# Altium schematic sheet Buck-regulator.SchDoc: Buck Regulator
size A4; Organization: Team- Ashwathama; Address1: Colorado Boulder; Address2: Author- Satya Mehta; Address3: Self Checkout Shopping Cart; DocumentNumber: 1; Revision: 1.0; SheetNumber: 3; SheetTotal: 7
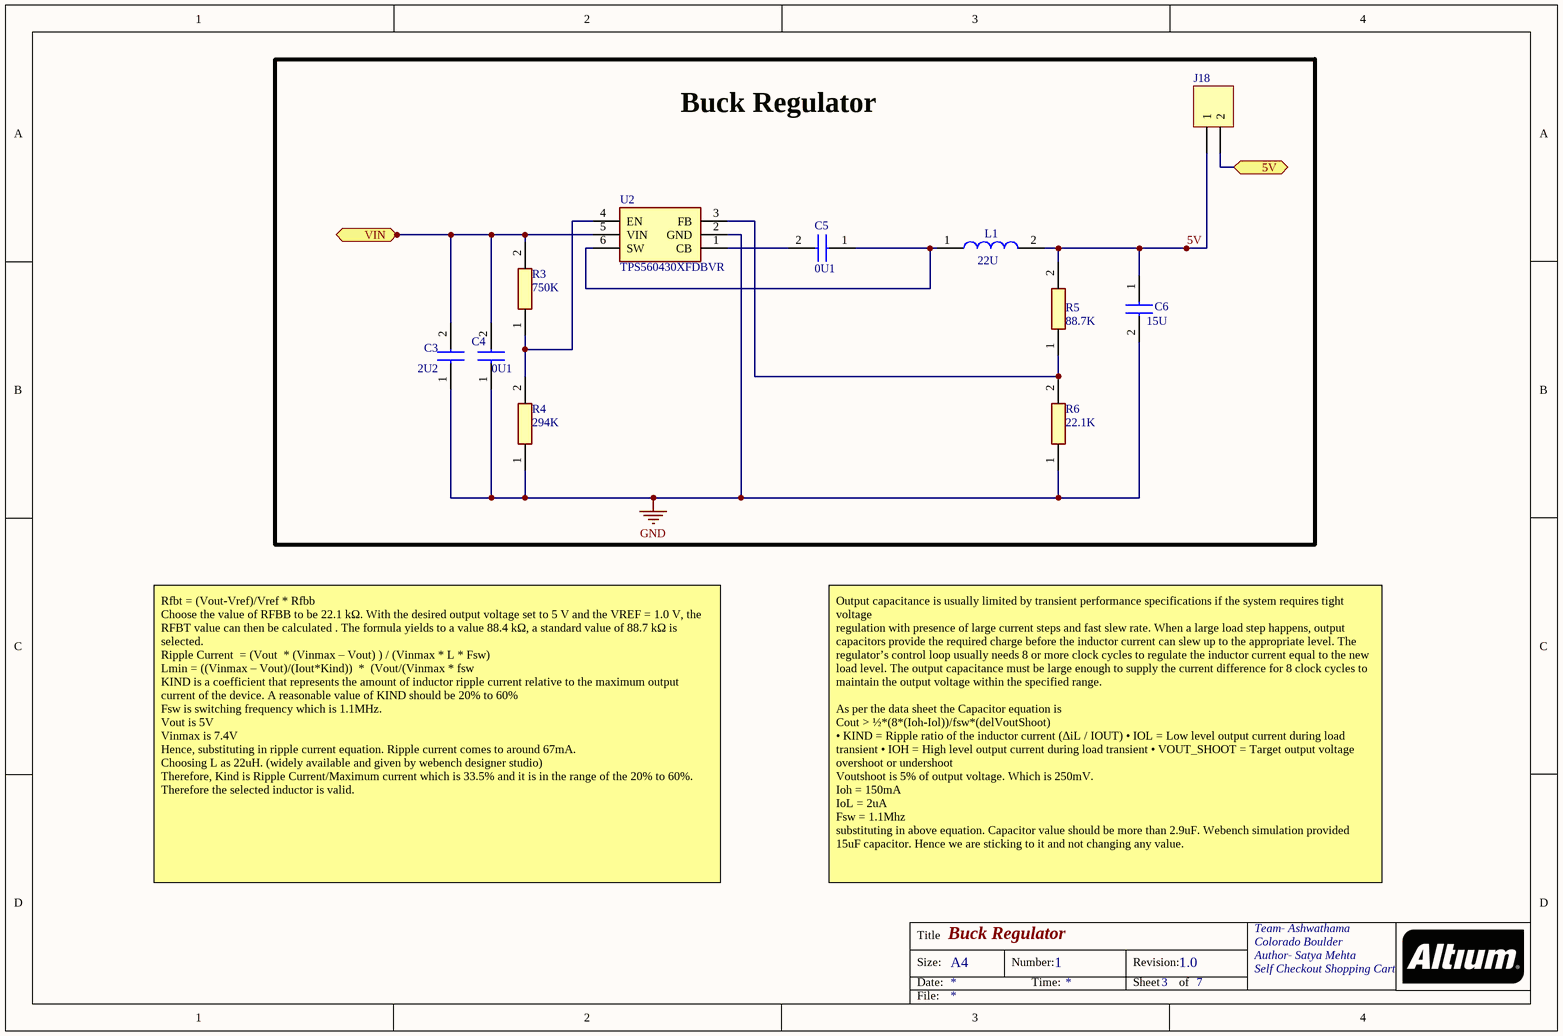
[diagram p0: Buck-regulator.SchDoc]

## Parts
C3  value 2U2  [CAPC2012X145N]  (hidden comment: GRM21BR71C225KA12L)
C4  value 0U1  [CAPC1608X87N]  (hidden comment: C0603C104K4RECTU)
C5  value 0U1  [CAPC1608X87N]  (hidden comment: C0603C104K4RECTU)
C6  value 15U  [CAPC1608X90N]  (hidden comment: GRM1885C2A150JA01D)
J18  Header 2  [HDR1X2]  (value not drawn)
L1  value 22U  [SRN3015]  (hidden comment: SRN3015-220M)
R3  value 750K  [RESC1608X55N]  (hidden comment: CR0603-FX-7503ELF)
R4  value 294K  [RESC1608X55N]  (hidden comment: CR0603-FX-2943ELF)
R5  value 88.7K  [RESC1608X50N]  (hidden comment: CRCW060388K7FKEA)
R6  value 22.1K  [RESC1608X55N]  (hidden comment: RC0603FR-0722K1L)
U2  TPS560430XFDBVR  [SOT95P280X145-6N]

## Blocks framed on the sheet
Buck Regulator: C3-C6 J18 L1 R3-R6 U2

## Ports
5V, VIN

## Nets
GND: C3.1 C4.1 C6.2 R4.1 R6.1 U2.2(GND)
5V: C6.1 J18.1 L1.2 R5.2
5V: J18.2 ; port 5V  [a separate net that carries the same name]
VIN: C3.2 C4.2 R3.2 U2.5(VIN) ; port VIN
NetC5_1: C5.1 L1.1 U2.6(SW)
NetC5_2: C5.2 U2.1(CB)
NetR3_1: R3.1 R4.2 U2.4(EN)
NetR5_1: R5.1 R6.2 U2.3(FB)

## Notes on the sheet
- Rfbt = (Vout-Vref)/Vref * Rfbb
  Choose the value of RFBB to be 22.1 kΩ. With the desired output voltage set to 5 V and the VREF = 1.0 V, the RFBT value can then be calculated . The formula yields to a value 88.4 kΩ, a standard value of 88.7 kΩ is selected.
  Ripple Current  = (Vout  * (Vinmax – Vout) ) / (Vinmax * L * Fsw)
  Lmin = ((Vinmax – Vout)/(Iout*Kind))  *  (Vout/(Vinmax * fsw
  KIND is a coefficient that represents the amount of inductor ripple current relative to the maximum output current of the device. A reasonable value of KIND should be 20% to 60%
  Fsw is switching frequency which is 1.1MHz.
  Vout is 5V
  Vinmax is 7.4V
  Hence, substituting in ripple current equation. Ripple current comes to around 67mA.
  Choosing L as 22uH. (widely available and given by webench designer studio)
  Therefore, Kind is Ripple Current/Maximum current which is 33.5% and it is in the range of the 20% to 60%. Therefore the selected inductor is valid.
- Output capacitance is usually limited by transient performance specifications if the system requires tight voltage
  regulation with presence of large current steps and fast slew rate. When a large load step happens, output
  capacitors provide the required charge before the inductor current can slew up to the appropriate level. The
  regulator’s control loop usually needs 8 or more clock cycles to regulate the inductor current equal to the new
  load level. The output capacitance must be large enough to supply the current difference for 8 clock cycles to
  maintain the output voltage within the specified range.
  As per the data sheet the Capacitor equation is
  Cout > ½*(8*(Ioh-Iol))/fsw*(delVoutShoot)
  • KIND = Ripple ratio of the inductor current (ΔiL / IOUT) • IOL = Low level output current during load transient • IOH = High level output current during load transient • VOUT_SHOOT = Target output voltage overshoot or undershoot
  Voutshoot is 5% of output voltage. Which is 250mV.
  Ioh = 150mA
  IoL = 2uA
  Fsw = 1.1Mhz
  substituting in above equation. Capacitor value should be more than 2.9uF. Webench simulation provided 15uF capacitor. Hence we are sticking to it and not changing any value.

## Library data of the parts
C3 = GRM21BR71C225KA12L: Capacitor; Manufacturer_Name: Murata Electronics
C4 C5 = C0603C104K4RECTU: Capacitor; Manufacturer_Name: Kemet
C6 = GRM1885C2A150JA01D: Capacitor; Manufacturer_Name: Murata Electronics
J18 = Header 2: Header, 2-Pin; Manufacturer_Part_Number: BG301-04-A-0540-L-B; Manufacturer_Name: Global Connector Technology
L1 = SRN3015-220M: Inductor; Manufacturer_Name: Bourns; Allied_Number: 70231649
R3 = CR0603-FX-7503ELF: Resistor; Manufacturer_Name: Bourns
R4 = CR0603-FX-2943ELF: Resistor; Manufacturer_Name: Bourns
R5 = CRCW060388K7FKEA: Resistor; Manufacturer_Name: Vishay; Allied_Number: 70203516
R6 = RC0603FR-0722K1L: Resistor; Manufacturer_Name: YAGEO (PHYCOMP)
U2 = TPS560430XFDBVR: Integrated Circuit; Manufacturer_Name: Texas Instruments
